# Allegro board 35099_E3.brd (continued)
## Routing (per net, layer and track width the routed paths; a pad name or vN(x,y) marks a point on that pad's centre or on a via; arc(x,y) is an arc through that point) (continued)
P1V8_CODEC: length 228.1
  TOP w0.203: C30.1 44.8,95.6 U8.6 ; C27.1 44.54,96.77 43.76,96 U8.7
  TOP w0.508: v1(101.43,7.49) U41.5 C337.1 J31.2 ; v1(8.66,2.91) 8.36,2.91 7.85,2.4 R377.1 ; U40.5 7.78,7.19 C336.1 8.47,7.55 v1(8.95,8.03) ; JS2.1 44.96,101.62 C21.1 C27.1 C30.1 ; R378.3 v1(100.66,3.99)
  L4_IN2 w0.508: v1(8.95,8.03) 8.95,43.42 2.05,50.32 2.05,65.81 25.82,89.57 v1(31.79,89.57)
  BOTTOM w0.508: v1(101.43,7.49) 100.66,6.72 v1(100.66,3.99) ; v1(8.95,8.03) 8.66,7.74 v1(8.66,2.91) 8.9,2.68 58.17,2.68 64.14,8.64 100.23,8.64 J31.2 J31.1
  vias: v1(32.41,90.46) v1(32.45,88.91) v1(33.22,89.66) v1(33.78,88.87) v1(33.87,90.53)
P5V_TRG_JTAG: length 6.5
  TOP w0.508: J19.13 78.87,76.93 78.36,76.42 TP12.1 77.65,79.17 77.6,79.22
VBAT: length 41.3
  TOP w0.254: U20.18 120.78,53.34 120.06,53.34 C80.1 R107.1 115.68,54.49 TP27.1 115.59,55.43 v1(115.99,55.83)
  L4_IN2 w0.508: v1(115.99,55.83) 124.12,55.83 125.86,57.57 141.82,57.57 J21.1
VBAT_BKUP: length 17.6
  TOP w0.203: U20.13 123.96,52.91 124.46,53.41 v1(124.5,53.41)
  TOP w0.254: R107.2 118.59,57.1 120.69,57.1 121.96,58.37 TP29.1 v1(126.44,58.37)
  L3_IN1 w0.508: v1(124.5,53.41) 124.5,56.42 v1(126.44,58.37)
  BOTTOM w0.254: C131.1 v1(124.5,53.41)
VBUS0_TARGET: length 63.7
  TOP w0.102: 97.22,61.77 97.22,61.43 97.38,61.28 98.17,61.28
  TOP w0.114: 97.22,61.77 U18.R16 ; v1(134.62,68.2) 133.78,67.36 121.11,67.36 115.02,61.28 98.17,61.28
  TOP w0.508: v1(148.67,78.28) R55.1 R54.2
  L4_IN2 w0.254: v1(148.67,78.28) 146.86,78.28 143.89,75.31 143.89,71.37 140.72,68.2 v1(134.62,68.2)
VDD1V8: length 38.2
  TOP w0.229: v2(96.47,62.52) U18.R15 ; U18.F13 v2(95.47,66.02) U18.G14 ; v2(95.47,70.02) U18.A13 ; v2(97.47,67.52) 97.47,67.52 U18.C17 U18.C16 ; v2(96.47,66.52) U18.E15 ; v2(93.97,68.02) U18.B11 ; v2(91.47,64.02) U18.L4
  L3_IN1 w0.229: v2(97.47,67.52) 97.47,67.74 96.69,68.52 94.47,68.52 v2(93.97,68.02)
  L3_IN1 w0.254: v2(97.47,67.52) 97.47,67.25 96.75,66.52 v2(96.47,66.52)
  L4_IN2 w0.229: v2(91.47,64.02) 91.47,63.62 90.55,62.7 90.55,61.85 90.86,61.54 95.79,61.54 96.47,62.22 v2(96.47,62.52) v2(96.47,66.52) 95.97,66.52 v2(95.47,66.02)
  BOTTOM w0.254: JP28.1 95.47,75.52 v2(95.47,70.02) 95.21,69.76 C118.1 94,69.29 C103.1 94,68.05 v2(93.97,68.02) ; C106.1 v2(96.47,66.52) ; C123.1 96.81,62.18 v2(96.47,62.52) ; C104.1 v2(91.47,64.02)
VDD_ACCEL: length 11.4
  TOP w0.254: U6.14 C29.1 C28.1 83.62,91.96 JP15.2
VDD_AMP: length 11.4
  L4_IN2 w0.508: v1(45.37,74.37) 45.37,71.57 47.28,69.67 47.28,68.27 47.03,68.02 46.39,68.02 45.14,66.77 v1(45.14,65.06)
  vias: v1(40.42,85.92) v1(41.06,85.92) v1(41.82,85.92)
VDD_CODEC: length 28
  TOP w0.203: U8.4 44.35,94.8 C33.1
  TOP w0.254: C329.1 51.44,97.84 U35.6 v1(54.41,97.84) U35.3 C333.1 ; v1(51.03,99.42) 51.46,99.85 R411.1 ; U36.3 v1(54.88,100.35) U36.6 ; R412.1 v1(59.03,100.56)
  TOP w0.508: JS3.1 47.4,100.8 47.4,94.99 46.16,93.75 C33.1
  BOTTOM w0.254: v1(51.03,99.42) 52.83,99.42 v1(54.41,97.84)
  vias: v1(34.12,99.33) v1(34.12,98.18) v1(34.76,98.82) v1(35.18,98.21) v1(35.31,99.35)
VDD_LDO_3V3: length 129.6
  TOP w0.381: U27.6 120.77,83.66 R50.1 121.42,83.57 v1(121.69,83.83) ; U28.6 119.9,86.53 120.26,86.88 C39.1 v1(121.92,86.88)
  TOP w0.508: R60.2 136.82,72.42 v1(136.72,72.52) ; v1(109.98,78.87) 109.98,77.76 SH4.1
  L3_IN1 w0.508: v1(121.92,86.88) 122.43,86.37 122.43,84.57 v1(121.69,83.83) 119.11,83.83 113.5,78.22 110.63,78.22 v1(109.98,78.87) 109.86,78.99 109.86,86.86 107.53,89.19 92.92,89.19 JP15.1
  L4_IN2 w0.508: v1(135.06,38.79) 135.06,26.09 JS15.2
  BOTTOM w0.508: v1(135.06,38.79) 134.37,39.48 134.37,56.77 136.72,59.12 v1(136.72,72.52) 125.4,83.83 v1(121.69,83.83)
VDD_LINK: length 16.5
  TOP w0.305: U5.6 104.53,97.33 C25.2 ; C36.2 104.57,90.75 U10.6 ; U2.6 105.77,106.06 105.75,106.07 C10.2
  TOP w0.381: 101.53,100.93 U3.8
  TOP w0.508: v1(105.97,98.17) 105.99,98.15 C25.2 ; v1(107.57,96.57) 107.06,96.06 R41.1 ; v1(102.04,99.84) 101.52,100.36 C16.2 101.53,100.93 ; R16.1 v1(103.02,109.5) ; C10.2 v1(105.16,105.05) ; v1(102.06,94.61) 101.57,94.13 R43.1 ; v1(111.89,119.81) 110.82,119.81 J2.1 ; v1(103.05,89.96) C36.2
  TOP w0.762: C12.1 JP2.2
VDD_MEM: length 28.1
  TOP w0.254: v1(63.04,53.82) 63.04,54.82 v1(63.54,55.32) R71.2 63.5,56.31 62.74,57.06 R362.1 ; v1(63.04,53.82) U19.B4 ; v1(63.04,53.82) 60.05,53.82 R69.1 ; R363.1 v1(57.54,51.32) ; U108.D1 v1(83.53,49.66) R240.1 ; U108.E4 v1(85.53,53.32) ; U108.B4 v1(82.05,52.8) ; U19.D1 v1(65.54,49.32) ; U19.E4 v1(67.04,53.82) ; R241.1 v1(78.53,54.32)
  BOTTOM w0.254: C130.1 67.03,53.81 v1(67.04,53.82) 67.05,53.81 C133.1 ; C219.1 82.05,52.01 v1(82.05,52.8) ; R71.2 v1(63.54,55.32) ; C129.1 63.03,53.82 v1(63.04,53.82) 63.08,53.85 C132.1 ; C128.1 65.55,49.32 v1(65.54,49.32) R66.1 C317.1 C128.1
  BOTTOM w0.508: C218.1 83.53,49.66 v1(83.53,49.66) ; C217.1 v1(85.53,53.32)
VDD_PMOD: length 103.4
  TOP w0.762: JS9.1 61.87,71.47 61.87,60.47 58.62,57.22 54.21,57.22 52.22,55.24 52.22,47.79 v1(45.67,41.23)
  BOTTOM w0.254: C134.2 J36.11
  BOTTOM w0.508: J36.12 J36.11
  BOTTOM w0.762: J36.11 4.06,22.11 4.85,21.33 25.76,21.33 v1(45.67,41.23)
VDD_RST: length 7.9
  TOP w0.254: U32.5 147.07,14.28 147.34,14.01 147.34,11.17 145.95,9.78 R132.2 144.65,9.78 144.46,9.59 U24.14
VDD_TARGET: length 168.2
  TOP w0.254: R1.1 v1(126.52,120.12) ; R123.1 v1(100.58,37.08) ; R98.1 JS13.2
  L4_IN2 w0.508: JS11.2 122.65,58.67 128.15,64.18 128.15,78.65 124.97,81.83 124.97,103.25 126.52,104.8 v1(126.52,120.12) ; v1(100.58,37.08) 104.01,37.08 107.31,40.39 139.08,40.39 JS13.2
  BOTTOM w0.254: JS11.2 122.03,58.67 128.27,52.43 128.27,47.88 119.96,39.57 106.63,39.57 104.14,37.08 v1(100.58,37.08)
VDDA_ADC1V8: length 13.5
  TOP w0.229: U18.E4 90.97,67.02 v2(90.47,66.52)
  BOTTOM w0.254: v2(90.47,66.52) 90.32,66.37 C109.1 81.1,66.37 JP25.2
VDDA_AO: length 24.3
  TOP w0.229: v2(95.97,67.52) U18.D13 U18.C13 v2(95.97,68.02)
  L3_IN1 w0.254: v1(109.86,67.86) 106.61,67.86 103.15,71.32 101.78,71.32 v1(100.52,72.58)
  L4_IN2 w0.254: JP26.2 v1(109.86,67.86)
  BOTTOM w0.229: C101.1 95.97,69.26 v2(95.97,68.02) 95.97,67.52 v2(95.97,67.52)
  BOTTOM w0.254: v1(100.52,72.58) 100.52,71.83 98.45,69.76 C101.1 ; C102.1 v2(95.97,68.02)
VDDA_BIAS: length 7.4
  TOP w0.229: U18.C4 90.97,68.52 v2(90.97,68.52)
  BOTTOM w0.254: C338.1 v2(90.97,68.52) 90.97,72.37 91.23,72.63 JP24.2
VDDCORE: length 9.4
  TOP w0.229: U18.J4 v2(91.47,65.02) ; v2(90.97,62.02) 90.97,62.02 U18.R5 ; U18.J14 v2(95.47,65.02) ; U18.F14 95.97,66.52 v2(95.47,67.02) ; U18.R14 v2(95.97,62.52) ; U18.P9 v2(93.47,63.02) ; U18.D9 v2(93.47,67.02) ; U18.C5 91.47,68.02 v2(90.97,67.52)
  BOTTOM w0.254: C126.1 v2(95.97,62.52) ; C119.1 v2(93.47,63.02) ; v2(93.47,67.02) 93.63,67.18 C112.1 ; C107.1 v2(90.97,67.52) ; C108.1 v2(95.47,67.02) ; v2(95.47,65.02) 95.31,64.87 C115.1 ; C125.1 v2(90.97,62.02) ; C114.1 v2(91.47,65.02)
VDDE_A: length 16.8
  TOP w0.203: v1(46.94,78.18) U12.A3 U12.B3 U12.C3 U12.C4 ; v1(47.14,67.26) U17.A3 U17.B3 U17.C3 U17.C4 U17.D4
  TOP w0.254: v1(47.14,67.26) 47.95,67.26 C71.1 ; U34.14 C328.1 48.53,82.84 v1(49.07,82.3) 49.28,82.09 49.28,79.27 48.49,78.49 C52.1 47.25,78.49 v1(46.94,78.18) ; U16.5 C63.1 52.03,67.26 v1(51.85,67.26)
  TOP w0.381: U15.5 52.47,73.28 v1(52.46,73.28)
VDDIO: length 12.8
  TOP w0.229: U18.P11 v2(94.47,63.02) U18.N12 U18.P12 U18.P11
  L3_IN1 w0.305: v2(94.47,63.02) U18.P12 95.43,62.07 97.17,62.07 JP27.1
  BOTTOM w0.229: C124.1 94.23,62.79 v2(94.47,63.02)
  BOTTOM w0.254: v2(94.47,63.02) 94.81,63.02 C105.1
VDDIO1: length 123.6
  TOP w0.203: U7.14 98.78,97.76 99.19,98.17 v1(99.3,98.17)
  TOP w0.254: R410.1 58.36,100.64 v1(58.06,100.64) 57.63,100.64 57.42,100.85 U36.7 ; v1(51.01,83.3) 51.01,83.31 U30.5 50.54,84.46 50.24,84.76 C322.1 ; R409.1 v1(51.59,102.16) ; R140.1 v1(75.72,100.82) ; v1(51.33,96.39) C330.1 51.38,97.19 U35.7 ; R139.1 v1(83.61,104.82) ; R138.1 v1(75.69,99.65) ; R137.1 v1(79.07,105.49)
  TOP w0.508: R116.1 v1(88.62,102.68) ; R383.1 R413.1 R414.1 v1(98.95,82.26) ; R130.1 v1(60.54,110.65) ; R10.1 v1(55.73,112.95) ; v1(97.09,97.62) 97.08,97.61 R39.2 ; R84.1 R83.1 127.51,46.22 C332.1 127.66,45.51 v1(127.69,45.49) ; R133.1 JP23.1 ; R58.1 v1(72.16,75.41) ; R145.1 v1(89.41,96.11) ; R117.1 v1(88.67,101.35) ; JS7.2 JS9.2
  TOP w0.762: D5.A JP2.1
  L3_IN1 w0.508: v1(51.01,83.3) 56.35,83.3 JS7.2 ; v1(127.69,45.49) 128.42,45.49 131.06,48.13 131.06,65.58 127.23,69.42 109.06,69.42 106.76,71.72 106.76,74.6 105.72,75.64 102.28,75.64 JP23.1
  BOTTOM w0.254: v1(51.59,102.16) 50.44,101.02 50.44,97.28 v1(51.33,96.39) ; v1(72.16,75.41) 70.25,77.32 70.25,86.48 70.67,86.89 R105.1
VDDIO1_MCU: length 28.6
  TOP w0.229: U18.K13 v2(95.97,64.52) U18.L14 ; U18.E6 v2(92.47,67.02) U18.E8 ; v2(94.97,65.52) U18.H13 U18.H14 ; v2(93.97,66.52) U18.E10
  L4_IN2 w0.229: v2(95.97,64.52) 95.97,65.27 95.72,65.52 v2(94.97,65.52) 94.22,65.52 93.97,65.77 v2(93.97,66.52) 92.97,66.52 v2(92.47,67.02)
  L5_PWR w0.229: v2(92.47,67.02) 92.47,68.12 93.57,69.22 98.46,69.22 102.19,72.94 102.19,75.53 JP23.2
  BOTTOM w0.254: v2(92.47,67.02) 92.63,66.87 C110.1 ; C117.1 v2(95.97,64.52) ; C113.1 v2(94.97,65.52)
ACC_INT1: length 5.4
  TOP w0.114: R40.1 R138.2 77.06,98.9 77.79,99.63 U6.11
ACC_INT2: length 6.6
  TOP w0.114: TP37.1 78.31,104.06 R137.2 79.07,101.09 79.54,100.63 U6.9
ACCEL_RST_8700: length 9.4
  TOP w0.114: R144.2 87.39,94.42 86.76,93.78 83.58,93.78 82.29,95.07 R141.1 U6.16
ALT_INT_AMP: length 14.3
  TOP w0.114: U34.5 45.19,84.93 v1(44.72,85.4)
  L3_IN1 w0.114: v1(44.72,85.4) 44.54,85.58 44.54,88.71 48.54,92.71 JP6.3
ALT_INT_CODEC: length 1
  TOP w0.114: R48.1 R401.2
BOOT0_LED: length 4.6
  TOP w0.254: R6.2 R7.1 132.23,114.83 132.42,114.65 U1.K2
BOOT1: length 3.7
  TOP w0.114: U1.K1 134.11,113.33 134.95,114.17 R9.1
BOOT2: length 5.6
  TOP w0.114: R29.2 v1(126.87,103.89)
  TOP w0.254: U1.C6 v3(128.82,107.33)
  BOTTOM w0.114: v3(128.82,107.33) 126.87,105.38 v1(126.87,103.89)
BOOT3: length 4
  TOP w0.114: U1.B10 R21.1
BRDG_INTR-ISP_DIR: length 27
  TOP w0.114: U1.J7 128.02,112.93 128.02,113.72 127.75,113.98 116.47,113.98 113.94,111.46 113.94,104.29 R25.1 113.81,103.1 U4.10
BRIDGE_INTR-ISP: length 219.2
  TOP w0.114: v1(64.14,64.25) 64.39,64.51 64.39,85 68.54,89.15 107.34,89.15 109.37,91.18 109.37,99.21 R36.1
  L3_IN1 w0.114: v1(111.38,54.74) 111.38,54.48 109.22,52.32 103.99,52.32 98.71,57.6 98.71,59.33 97.23,60.81 88.95,60.81 86.19,63.57 74.97,63.57 72.97,65.57 65.45,65.57 v1(64.14,64.25) 61.51,64.25 33.18,35.93 23.38,35.93 v1(23.37,35.94)
  L4_IN2 w0.114: JP13.2 138.3,56.39 126.87,56.39 125.22,54.74 v1(111.38,54.74)
  BOTTOM w0.114: R108.1 v1(23.37,35.94)
BRIDGE_L_INTR-ISP: length 33.1
  TOP w0.114: U1.J5 129.63,112.92 129.63,113.7 129.02,114.3 116.44,114.3 113.39,111.24 v1(113.39,107.47) ; R34.2 120.9,103.42 119.55,104.78 117.5,104.78 115.29,106.98 v1(114.55,106.98)
  BOTTOM w0.114: v1(114.55,106.98) 113.87,106.98 v1(113.39,107.47)
BRIDGE_L_MISO: length 40.7
  TOP w0.114: U26.2 v1(120.83,96.21) ; U1.J1 135.08,112.53 135.71,113.16 v1(135.76,113.16)
  BOTTOM w0.114: v1(135.76,113.16) 135.76,116.2 134.52,117.45 127.99,117.45 122.02,111.48 122.02,106.3 119.61,103.89 119.61,97.43 v1(120.83,96.21)
BRIDGE_L_MOSI: length 32.6
  TOP w0.114: U4.6 118.78,102.6 119.53,103.35 v1(120.19,103.35) ; v1(135.03,113.61) 134.34,112.93 132.82,112.93 U1.J2
  BOTTOM w0.114: v1(135.03,113.61) 135.33,113.92 135.33,115.85 134.18,117.01 128.36,117.01 122.38,111.02 122.38,105.54 v1(120.19,103.35)
BRIDGE_L_SCK: length 31.1
  TOP w0.114: U4.4 121.06,101.6 121.49,102.03 121.49,103.33 119.79,105.03 117.73,105.03 114.33,108.43 114.33,111.5 116.57,113.74 126.4,113.74 U1.K9
BRIDGE_L_SSEL: length 30.2
  TOP w0.114: U1.K10 116.55,113.33 114.76,111.53 114.76,108.51 117.98,105.28 120.14,105.28 121.84,103.58 121.84,101.83 121.12,101.1 U4.3
BRIDGE_UART_RXD: length 25
  TOP w0.114: v1(123.62,110.97) 123.67,110.93 U1.G10 ; v1(120.35,91.55) U9.4
  BOTTOM w0.114: v1(120.35,91.55) 121.52,91.55 123.62,93.65 v1(123.62,110.97)
BRIDGE_UART_TXD: length 27.7
  TOP w0.114: U9.5 120.84,92.05 v1(121.04,92.24)
  TOP w0.254: U1.G7 v3(128.02,111.33)
  BOTTOM w0.114: v1(121.04,92.24) 123.12,94.33 123.12,111.19 123.83,111.9 125.02,111.9 125.14,111.79 127.56,111.79 v3(128.02,111.33)
BT_REG_ON_3V3: length 81.1
  TOP w0.114: C319.1 Q16.3 v1(133.99,24.4) ; v1(72.33,31.93) J45.54 72.33,29.54 73.55,28.32 v1(76.2,28.32)
  L3_IN1 w0.114: v1(133.99,24.4) 80.12,24.4 v1(76.2,28.32)
  BOTTOM w0.114: v1(72.33,31.93) 71.75,31.36 R227.2
BYP_8700: length 4.1
  TOP w0.114: C31.1 86.13,99.13 U6.2
CARD_WR_PRT: length 26
  TOP w0.114: v1(109.64,29.03) 109.6,29.06 J32.11
  TOP w0.254: v1(122.34,36.65) 122.38,36.69 R308.2 R307.1
  L4_IN2 w0.114: v1(109.64,29.03) 110.61,28.06 122.13,28.06 122.84,28.77 122.84,30.17 121.7,31.32 121.7,36.01 v1(122.34,36.65)
CPCA: length 4.8
  TOP w0.203: C20.1 44.09,99.92 44.09,97.66 43.38,96.95 U8.8
CPCB: length 3
  TOP w0.203: C20.2 42.4,98.54 U8.10
CRST_8700: length 3.5
  TOP w0.114: U6.8 81.29,103.24 C143.1
CS_AP: length 4.4
  TOP w0.114: U108.A3 81.03,52.82 81.03,55.8 R248.2
CS_MX: length 3.2
  TOP w0.114: U19.C2 65.04,50.82 R350.2
DCDC_3V3: length 210.4
  TOP w0.762: C85.1 J28.8
  TOP w1.016: C85.1 10.81,50.55 11.79,49.57 11.79,46.63 16.14,42.28 16.14,5.38 J29.2
  L3_IN1 w0.508: J29.4 21.23,5.4 25.56,9.72 83.47,9.72 85.63,7.57 99.22,7.57 100.11,6.68 102.65,6.68 103.67,7.69 129.58,7.69 132.82,4.45 141.22,4.45 144.15,7.37 144.15,11.94 145.74,13.54 147.99,13.54 150.28,15.82 150.28,17.74 148.08,19.94 146.94,19.94 145.6,21.28 JS15.1
  L4_IN2 w0.508: J29.2 17.61,6.83 19.78,6.83 J29.4
DQS_AP: length 4.4
  TOP w0.114: R246.2 83.03,55.8 83.03,52.82 U108.C3
DQS_MX: length 5.4
  TOP w0.114: U19.C3 65.04,51.82 69.03,51.82 R353.2
ELECTRET_MIC: length 47.7
  TOP w0.203: R49.3 34.65,87.71 31.43,87.71 30.87,88.27 30.87,93.92 R42.1
  TOP w0.254: v1(32.11,96.34) R42.1
  BOTTOM w0.254: v1(32.11,96.34) 21.17,96.34 18.03,99.48 11.27,99.48 3.68,107.06
  BOTTOM w0.508: 3.68,107.06 4.01,107.39 D14.1
FC0_RXD: length 9
  TOP w0.114: U28.4 120.22,85.23 R50.2 122.94,84.58 J16.2
FC0_TXD: length 8.6
  TOP w0.114: U27.4 123.25,82.36 J16.1
FC1_CTS_SDA_SSEL0: length 90.4
  TOP w0.114: J47.4 41.55,59.65 R408.2 ; J31.14 86.11,11.89 86.11,38.86 v1(84.07,40.89) 84.13,40.95 R396.3
  BOTTOM w0.114: v1(84.07,40.89) 83.19,41.78 76.36,41.78 72.04,46.1 61.48,46.1 56.02,51.56 41.54,51.56 40.28,52.82 40.28,54.86 41.59,56.17 J47.4
FC1_SCK: length 6.9
  TOP w0.114: R394.3 J47.1
FC1_TXD_SCL_MISO: length 10.2
  TOP w0.114: J47.2 47.71,60.73 55.42,60.73 R395.3
FC2_SCK: length 18.6
  TOP w0.114: J47.5 40.79,61.43 50.78,61.43 52.59,63.24 R397.3
FC4_CTS_SDA_SSEL0: length 29.5
  TOP w0.114: J47.9 30.87,61.67 50.68,61.67 54.02,65.02 R398.3
FC5_CTS: length 2.7
  TOP w0.114: J45.34 v1(67.33,32.44)
  BOTTOM w0.114: v1(67.33,32.44) 67.53,32.64 R212.2
FC5_RTS: length 2.9
  TOP w0.114: J45.36 v1(67.83,31.93)
  BOTTOM w0.114: v1(67.83,31.93) 68.48,32.58 R213.2
FC5_RXD: length 2.8
  TOP w0.114: J45.22 v1(64.33,31.93)
  BOTTOM w0.114: v1(64.33,31.93) 64.67,32.27 R210.2
FC5_TXD: length 2.7
  TOP w0.114: J45.32 v1(66.83,31.93)
  BOTTOM w0.114: R211.2 66.58,32.18 v1(66.83,31.93)
HP_OUTL: length 31.8
  TOP w0.203: U8.13 41.2,98.57 40.36,99.42 40.36,100.94 40.02,101.28 34.35,101.28 C15.1 33.05,102.59 33.05,103.66 C11.1 33.78,108.64 J4.2
  TOP w0.254: J4.2 35.15,109.52 42.38,109.52 D3.1
HP_OUTR: length 40.9
  TOP w0.203: U8.15 40.4,98.79 C17.1 39.05,99 37.48,99 36.07,100.41 34.08,100.41 32.16,102.33 32.16,111.07 35.31,114.22 D3.2
  TOP w0.254: D3.2 45.21,114.24 C2.1 42.38,117.09 J4.3
I2C_SA0_8700: length 4.8
  TOP w0.114: U6.7 81.79,102.01 82.82,103.04 R139.2 82.81,104.07 R135.1
I2C_SA1_8700: length 5.5
  TOP w0.114: U6.10 79.27,100.13 77.83,101.57 R140.2 76.57,102.53 R136.1
I2PIO2_0-SD0_D(0)_SCL: length 18.6
  TOP w0.114: JS6.1 R126.2
  TOP w0.254: U1.D6 v3(128.82,108.13)
  BOTTOM w0.114: JS6.1 130.56,98.81 129.53,99.83 126.83,99.83 126.19,100.48 126.19,106.85 127.06,107.72 128.4,107.72 v3(128.82,108.13)
I2PIO2_0-SD0_D(0)_SDA: length 16.4
  TOP w0.114: JS5.1 R127.2
  TOP w0.254: U1.E6 v3(128.82,108.93)
  BOTTOM w0.114: JS5.1 126.49,99.45 125.78,100.16 125.78,107.04 127.26,108.52 128.4,108.52 v3(128.82,108.93)
I2S_ALT_INT: length 17.1
  TOP w0.114: v1(44.85,80.95) 45.19,81.3 U34.10 ; U15.4 51.59,74.1 53.1,75.62 53.1,80.19 52.38,80.92 v1(50.97,80.92)
  BOTTOM w0.114: v1(44.85,80.95) 44.85,80.96 45.31,81.42 50.47,81.42 v1(50.97,80.92)
I2S_BCLK_AMP: length 16.8
  TOP w0.114: U17.B1 45.54,68.44 v1(45.86,68.76) ; U34.12 46.12,81.73 v1(46.12,80.7) 45.54,80.12 U12.B1
  TOP w0.152: U12.B2 U12.B1 ; U17.B2 U17.B1
  BOTTOM w0.114: v1(45.86,68.76) 45.86,80.45 v1(46.12,80.7)
I2S_BCLK_CODEC: length 73.4
  TOP w0.114: v1(54.12,50.51) v1(54.12,55.11)
  TOP w0.152: R400.2 42.41,87.68 41.15,88.95 v1(41.15,89.53) 41.6,89.99 U8.29
  BOTTOM w0.114: R215.2 60.13,34.69 60.13,35.92 59.69,36.36 59.69,37.17 54.36,42.5 54.36,50.16 54.12,50.4 v1(54.12,50.51) ; v1(41.15,89.53) 41.15,88.8 42.24,87.71 48.06,87.71 51.94,83.82 51.94,82.04 52.96,81.03 52.96,73.15 54.49,71.62 54.49,55.47 v1(54.12,55.11)
I2S_DAI_AMP: length 19.9
  TOP w0.114: v2(44.74,79.95) 45.69,80.9 U34.11
  TOP w0.152: v2(44.74,79.95) U12.D1 ; v2(44.74,68.51) U17.D1
  L4_IN2 w0.152: v2(44.74,79.95) 44.19,79.95 43.78,80.36 41.98,80.36 41.58,79.96 41.58,73.81 44.74,70.65 v2(44.74,68.51)
I2S_DAI_CODEC: length 70.7
  TOP w0.114: v1(55.61,50.58) v1(55.61,55.11) ; R404.2 v1(42.37,89.52)
  TOP w0.152: v1(42.37,89.52) 42.4,89.55 U8.31
  BOTTOM w0.114: R217.2 61.81,36.36 55.14,43.03 55.14,50.11 v1(55.61,50.58) ; v1(42.37,89.52) 47.39,89.52 53.85,83.06 53.85,75.06 55.37,73.53 55.37,55.35 v1(55.61,55.11)
I2S_DAO_AMP: length 39.6
  TOP w0.152: U17.C1 v2(45.14,68.78) ; U12.C1 v2(45.14,79.56)
  L3_IN1 w0.076: v2(45.14,79.56) 45.13,79.55 44.35,79.55 44.29,79.6
  L3_IN1 w0.114: 44.29,79.6 43.96,79.94 43.96,88.63 49.11,93.78 55.06,93.78 JP7.3
  L4_IN2 w0.152: v2(45.14,68.78) 45.14,70.79 41.9,74.03 41.9,76.31 v2(45.14,79.56)
I2S_DAO_CODEC: length 87.6
  TOP w0.114: v1(56.39,55.12) 56.05,54.78 56.05,50.08 v1(55.63,49.66) ; U8.32 42.8,91.44 v1(43.08,91.16) R402.2 ; U35.4 v1(55.9,98.49)
  L4_IN2 w0.114: v1(55.9,98.49) 52.58,95.18 49.17,95.18 45.15,91.16 v1(43.08,91.16)
  BOTTOM w0.114: R218.2 62.77,35.94 55.63,43.08 v1(55.63,49.66) ; v1(43.08,91.16) 43.08,90.91 44.07,89.92 47.5,89.92 54.48,82.93 54.48,75.31 55.75,74.04 55.75,55.75 v1(56.39,55.12)
I2S_WS_AMP: length 16.5
  TOP w0.114: v1(46.63,68.75) U17.A1 ; U12.A1 45.94,79.5 v1(46.69,80.26) U34.13
  BOTTOM w0.114: v1(46.63,68.75) 47.66,69.78 47.66,79.29 v1(46.69,80.26)
I2S_WS_CODEC: length 71.3
  TOP w0.114: R399.2 42.15,88.63 v1(41.81,88.98) ; v1(54.87,50.54) v1(54.87,55.09)
  TOP w0.152: v1(41.81,88.98) 41.81,89.71 42,89.91 U8.30
  BOTTOM w0.114: v1(41.81,88.98) 47.29,88.98 53.34,82.93 53.34,73.79 54.87,72.26 v1(54.87,55.09) ; v1(54.87,50.54) 54.74,50.4 54.74,42.67 60.07,37.34 60.07,36.32 60.58,35.81 60.58,34.75 R216.2
IF_DETECT: length 42.3
  TOP w0.114: R28.1 123.93,102.11 120.5,105.53 118.19,105.53 115.21,108.51 v1(115.21,111.37)
  TOP w0.508: J2.9 105.64,119.86 v1(104.42,119.86) JS1.2
  L3_IN1 w0.114: v1(104.42,119.86) 109.3,119.86 114.68,114.48 114.68,111.9 v1(115.21,111.37)
IF_JTAG_TDI: length 25.9
  TOP w0.114: R26.2 98.3,104.62 98.3,105.05 95.2,108.15 95.2,110.9 96.34,112.04 105.65,112.04 106.98,113.37 v1(106.98,113.45) 106.98,115.77 J2.8
  BOTTOM w0.114: D13.1 106.98,114.71 v1(106.98,113.45)
IF_RST: length 243.5
  TOP w0.114: JP17.1 94.56,93.66 92.1,96.13 92.1,104.92 94.02,106.84 94.02,111.26 96.6,113.84 v1(105.54,113.84) 105.54,115.7 J2.10 ; v1(76.33,85.32) J19.10 ; SH11.1 75.69,112.01 77.37,110.34 77.37,107.9 73.28,103.81 73.28,93.11 v1(74.93,91.46) ; U24.9 v1(140.53,11.46)
  L3_IN1 w0.114: v1(75.56,25.78) 75.56,24.11 85,14.68 137.32,14.68 v1(140.53,11.46)
  L4_IN2 w0.114: v1(74.93,91.46) 74.93,88.9 75.56,88.27 75.56,86.08 v1(76.33,85.32) 77.6,84.04 77.6,59.16 74.44,56 74.44,39.98 75.56,38.86 v1(75.56,25.78)
  BOTTOM w0.114: v1(105.54,113.84) 105.54,115.31 106.29,116.07 D13.3 ; R148.2 102.36,85.72 101.47,86.61 100.84,86.61 100.2,87.25 100.2,89.66 99.06,90.81 95.76,90.81 94.6,91.96 JP17.1 88.58,85.98 76.99,85.98 v1(76.33,85.32)
IF_TCK_SWCLK: length 93
  TOP w0.114: SH13.1 v1(75.79,109.35) ; v1(72.52,85.41) J19.4 ; v1(109.45,113.82) 109.45,115.8 J2.4 ; U7.3 v1(92.99,95.91) 92.99,103.12 JP18.1 94.56,111.15 95.83,112.42 104.83,112.42 v1(105.41,113)
  L3_IN1 w0.114: v1(92.99,95.91) 91.11,97.79 84.84,97.79 75.31,107.31 75.31,108.86 v1(75.79,109.35)
  BOTTOM w0.114: v1(72.52,85.41) 72.52,86.07 R104.1 72.96,86.14 73.28,86.46 73.28,87.07 74.46,88.26 79.84,88.26 86.76,95.18 92.25,95.18 v1(92.99,95.91) ; D13.6 109.21,114.05 v1(109.45,113.82) 108.64,113 v1(105.41,113)
IF_TDO_SWO: length 112.7
  TOP w0.114: J2.6 v1(108.2,114.02) 105.84,111.66 96.75,111.66 95.68,110.59 95.68,108.79 98.95,105.52 102.14,105.52 105.16,102.5 105.16,101.55 106.63,100.08 107.54,100.08 108.13,99.49 108.13,95.72 107.79,95.38 106.27,95.38 105.99,95.66 R41.2 104.53,96.06 U5.4 103.64,96.05 103.21,95.62 v1(100.72,95.62) 100.03,96.31 U7.11 ; v1(73.79,86.74) J19.6
  TOP w0.254: v1(73.56,91.51) 72.84,92.22 72.84,104.16 76.83,108.15 76.83,110.13 76.32,110.65 SH12.1
  L4_IN2 w0.254: v1(73.79,86.74) 73.56,86.97 v1(73.56,91.51)
  BOTTOM w0.114: D13.4 108.48,116.07 108.2,115.79 v1(108.2,114.02) ; v1(73.79,86.74) 74.65,87.6 80.62,87.6 86.61,93.6 92.33,93.6 93.82,95.09 100.19,95.09 v1(100.72,95.62)
INB_2: length 1.3
  TOP w0.229: 43.54,68.58 U17.G1 U17.G2 U17.G3
INT1_AMP: length 8.2
  TOP w0.152: U12.A5 46.41,76.91 48.94,76.91 49.76,77.72 51.86,77.72 52.47,77.12 U15.1
INT2_AMP: length 15.9
  TOP w0.152: U17.A5 46.62,65.77 48.97,65.77 51.8,68.61 51.8,69.38 50.7,70.49 50.7,74.84 51.82,75.96 U15.2
INT_B: length 61.4
  TOP w0.114: v1(110.65,72) 110.23,71.58 109.45,71.58 109.44,71.57 108.13,71.57 107.18,72.52 106.93,72.77 101.67,72.77 99.04,70.15 97.05,70.15 96.47,69.57 U18.A15
  TOP w0.203: U20.10 v1(126.53,51.55) R85.2
  L4_IN2 w0.114: v1(110.65,72) 111.25,71.39 111.25,64.39 107.19,60.33 107.19,53.21 108.08,52.32 111.12,52.32 112.96,50.49 125.83,50.49 126.53,51.19 v1(126.53,51.55)
JTAG_RESET: length 35.8
  TOP w0.114: U10.3 106.75,93.13 108.73,95.11 108.73,101.09 111.18,103.53 111.18,105.54 111.89,106.25 v1(113.33,106.25) ; U1.D10 125.25,109.3 120.42,109.3 119.91,109.8 119.91,111.07 119.53,111.46 117.68,111.46 117.48,111.26 117.48,109.1 v1(116.54,108.15)
  BOTTOM w0.114: v1(116.54,108.15) 114.63,106.25 v1(113.33,106.25)
JTAG_RESET_TXEN: length 44.8
  TOP w0.114: R47.1 102.97,91.41 U10.5 105.49,91.41 105.74,91.16 105.74,90.32 106.16,89.9 v1(106.77,89.9) ; v1(124.49,111.38) 124.54,111.33 126.42,111.33 U1.G9
  BOTTOM w0.114: v1(124.49,111.38) 124.49,110.88 124,110.4 124,93.4 120.51,89.9 v1(106.77,89.9)
JTAG_TDI: length 24.9
  TOP w0.114: U1.J10 125.95,112.6 117.65,112.6 116.34,111.28 v1(116.34,109.64) ; v1(112.42,108.23) 110.26,106.07 110.26,104.19 108.3,102.23 U3.3
  BOTTOM w0.114: v1(116.34,109.64) 113.83,109.64 v1(112.42,108.23)
JTAG_VREF: length 46
  TOP w0.114: R58.2 71.25,76.44 J19.1 70.14,79.22 69.91,79.46 69.91,85.24 v1(68.13,87.02) ; J38.12 R130.2 v1(63.22,110.01) J38.14
  L3_IN1 w0.114: v1(68.13,87.02) 68.13,92.65 59.56,101.22 59.56,108.97 60.61,110.01 v1(63.22,110.01)
LDO1_OUT: length 179.4
  TOP w0.381: R3.1 124.08,119.09 v1(123.08,118.08) 122.1,117.11 R124.1
  TOP w0.508: TP17.1 127.67,61.2 v1(125.17,63.7) ; TP17.1 128.93,54.06 R82.1 R85.1 ; TP17.1 127.16,54.81 C84.1 125.42,53.41 U20.12 ; 145.61,8.26 v1(146.85,8.26) ; R67.1 v1(129.4,50.03) ; v1(141.26,34.62) 142.15,34.62 ; R70.1 v1(129.45,48.1) ; R149.1 v1(115.52,73.99)
  L3_IN1 w0.508: TP17.1 129.4,53.58 v1(129.4,50.03) 130.03,49.4 130.03,48.68 v1(129.45,48.1) 128.49,48.1 126.49,46.1 126.49,44.2 136.07,34.62 v1(141.26,34.62) 142.68,34.62 151.17,26.13 151.17,12.57 v1(146.85,8.26)
  L4_IN2 w0.762: v1(123.08,118.08) 123.08,117.6 ; v1(109.09,85.72) 109.09,77.77 109.86,77.01 JP26.1 110.57,73.15 112.35,74.93 114.58,74.93 v1(115.52,73.99) 115.43,73.9 115.43,70.99 122.73,63.7 v1(125.17,63.7)
  L4_IN2 w1.016: v1(115.52,73.99) 116.46,73.99 120.02,77.54 120.02,79.76 123.45,83.19 123.45,101.47 122.69,102.23 122.69,112.31 123.08,112.7 123.08,117.6
  BOTTOM w0.508: 106.3,85.72 v1(109.09,85.72)
LDO2_OUT: length 102.2
  TOP w0.114: JP12.3 103.08,79.41 R89.1
  TOP w0.203: v1(123.06,53.52) U20.15
  TOP w0.254: R308.1 124.45,37.71 v1(124.5,37.66) 124.51,37.65 R310.1
  TOP w0.508: R309.1 R310.1
  L3_IN1 w0.508: v1(123.06,53.52) 123.13,53.58 TP15.1 119.63,61.11 JS11.1 107.95,58.67 106.75,57.47 JP27.2
  BOTTOM w0.508: JP12.3 107.55,79.44 109.22,81.12 113.94,81.12 118.02,77.03 118.02,66.22 TP15.1 125.58,61.11 130.72,55.97 130.72,43.89 v1(124.5,37.66)
LDO_ENABLE: length 18.6
  TOP w0.114: v1(104.34,71.84) 104.33,71.83 101.41,71.83 99.24,69.66 97.18,69.66 96.97,69.45 U18.A16
  BOTTOM w0.114: JP22.2 111.01,69.22 106.97,69.22 v1(104.34,71.84)
LED_BLUE: length 3.5
  TOP w0.152: Q3.7 149.54,46.94 Q3.6 149.54,48.79 D8.C
LED_GREEN: length 3.3
  TOP w0.152: Q4.8 150.24,41.71 Q4.3 150.66,40.93 D10.C
LED_RED: length 2.3
  TOP w0.152: D9.C 150.54,43.56 149.54,42.55 Q4.6 149.54,41.86 Q4.7
LININL: length 43.1
  TOP w0.203: U8.26 40.4,92.22 39.52,91.34 39.52,87.91 35.28,83.67 33.12,83.67 29.31,87.48 29.31,110.74 28.8,111.25 C7.1
LININL_JACK: length 29.8
  TOP w0.508: R19.1 C8.1 C7.2 25.21,111.25 D4.1 23.15,109.35 15.88,109.35 v1(15.44,109.78) 15.43,109.77 J3.2
  BOTTOM w0.508: P1.1 4.01,109.27 D14.2 13.07,109.27 13.58,109.78 v1(15.44,109.78)
LININR: length 10.7
  TOP w0.203: R49.2 36.66,86.16 38.81,88.3 38.81,93.27 39.14,93.6 U8.24
LININR_JACK: length 11.2
  TOP w0.508: J3.3 21.17,117.17 D4.2 25.21,113.28 C6.2 C4.1 R4.1
LINK2_ISP_BOOT: length 8.9
  TOP w0.114: U1.C10 119.88,107.73 118.62,108.99 JP1.1
M2_32K_3V3: length 15.7
  TOP w0.114: J45.50 71.33,31.93 74.31,34.91 79.27,34.91 80.39,33.78 80.39,32.38 R423.2 R200.2
M2_SD_CDM: length 74.2
  TOP w0.114: R202.1 v1(60.23,43.04) ; v1(125.6,36.02) 126.36,36.02 R303.3
  BOTTOM w0.114: v1(125.6,36.02) 125.2,35.61 111.65,35.61 110.4,34.36 83.09,34.36 72.12,45.34 62.52,45.34 v1(60.23,43.04)
M2_SD_CLK: length 67.8
  TOP w0.114: R201.1 v1(59.27,43.04) ; v1(118.82,36.05) 118.83,36.05 R302.3
  BOTTOM w0.114: v1(118.82,36.05) 111.62,36.05 110.17,34.6 83.19,34.6 72.08,45.72 61.95,45.72 v1(59.27,43.04)
M2_SD_DAT0: length 62.4
  TOP w0.114: R203.1 v1(61.18,43.04) ; R301.3 115.4,35.3 v1(115.84,34.85)
  BOTTOM w0.114: v1(115.84,34.85) 111.65,34.85 110.92,34.12 82.89,34.12 72.05,44.96 63.1,44.96 v1(61.18,43.04)
M2_SD_DAT1: length 57.4
  TOP w0.114: R204.1 v1(62.13,43.04) ; R300.3 112.72,35.3 v1(111.83,34.41)
  BOTTOM w0.114: v1(62.13,43.04) 63.67,44.58 71.98,44.58 82.68,33.88 111.3,33.88 v1(111.83,34.41)
M2_SD_DAT2: length 76.4
  TOP w0.114: R305.3 130.93,36.45 v1(127.46,36.45) ; R205.1 v1(63.08,43.04)
  BOTTOM w0.114: v1(63.08,43.04) 64.24,44.2 71.91,44.2 82.47,33.64 116.44,33.64 118.09,35.29 126.3,35.29 v1(127.46,36.45)
M2_SD_DAT3: length 78.1
  TOP w0.114: R206.1 v1(64.04,43.04) ; v1(130.7,34.85) 130.26,35.3 R304.3
  BOTTOM w0.114: v1(64.04,43.04) 64.81,43.81 71.85,43.81 83.08,32.58 115.89,32.58 118.29,34.98 124.15,34.98 125.93,33.2 131.11,33.2 131.42,33.5 131.42,34.13 v1(130.7,34.85)
M2_SD_RST_B: length 63.4
  TOP w0.114: v1(122.32,33.07) 121.56,32.31 R306.3 ; R208.1 v1(65.94,43.04)
  BOTTOM w0.114: v1(65.94,43.04) 71.72,43.04 82.66,32.1 121.34,32.1 v1(122.32,33.07)
M2_SD_WK_B: length 66.7
  TOP w0.114: v1(124.1,33.07) 123.33,32.31 R307.3 ; R207.1 v1(64.99,43.04)
  BOTTOM w0.114: v1(124.1,33.07) 123.59,33.58 121.97,33.58 120.73,32.34 82.87,32.34 71.73,43.48 65.43,43.48 v1(64.99,43.04)
M2_USB_DN: length 160.1
  TOP w0.114: R222.1 v1(146.2,83.87) ; v1(59.41,35.41) 59.16,35.65 59.16,36.05 59.95,36.83 59.95,37.2 60.08,37.33 J45.5
  BOTTOM w0.114: v1(59.41,35.41) 59.17,35.17 59.17,34.81 58.85,34.49 57.3,34.49 56.57,33.76 56.57,28.87 60.92,24.51 125.48,24.51 136.53,35.56 136.53,42.8 135.64,43.69 135.64,56.13 138.68,59.18 138.68,74.42 146.43,82.17 147.36,82.17 148.97,83.78 148.97,84.79 147.77,85.99 147.73,85.99 146.32,85.99 146.2,85.87 v1(146.2,83.87)
M2_USB_DP: length 161.2
  TOP w0.114: R221.1 v1(146.2,88.34) ; J45.3 59.58,37.33 59.71,37.2 59.71,36.93 58.92,36.15 58.92,35.65 58.68,35.41 v1(58.68,35.39)
  BOTTOM w0.114: v1(58.68,35.39) 58.93,35.14 58.93,34.91 58.75,34.73 57.2,34.73 56.32,33.86 56.32,28.77 60.82,24.27 125.58,24.27 136.77,35.46 136.77,42.9 135.88,43.79 135.88,56.03 138.93,59.08 138.93,74.32 146.53,81.93 147.46,81.93 149.21,83.68 149.21,84.89 147.87,86.23 147.67,86.23 146.32,86.23 146.2,86.34 v1(146.2,88.34)
MCLK_CODEC: length 18.5
  TOP w0.114: U35.5 49.83,98.49 R403.2 v1(48.59,97.25) ; U8.28 41.2,91.91 v1(40.91,91.62)
  L3_IN1 w0.114: v1(48.59,97.25) 48.59,93.84 46.37,91.62 v1(40.91,91.62)
MEM_1V8: length 10.4
  TOP w0.114: v1(76.54,50.32) 76.66,50.44 R249.1 ; R250.1 v1(79.53,57.81)
  L4_IN2 w0.114: v1(79.53,57.81) 79.53,53.32 v1(76.54,50.32)
MICBIAS: length 7.2
  TOP w0.203: U8.20 38,95.2
  TOP w0.254: C32.1 36.83,94.97 36.17,94.31 33.96,94.31 R42.2
  TOP w0.381: C32.1 36.88,95.2 38,95.2
MICVDD: length 3.9
  TOP w0.203: C26.1 38.57,95.6 U8.19
  TOP w0.381: C26.1 37.37,96.79 L2.2
MODESEL0: length 64.1
  TOP w0.114: v1(108.88,72.01) 108.88,72 107.87,73.01 101.57,73.01 98.94,70.39 96.95,70.39 96.22,69.65 96.22,68.28 U18.C15
  TOP w0.203: R81.1 R70.2 v1(126.98,48.78) 126.98,49.11 125.94,50.15 U20.7
  L4_IN2 w0.114: v1(126.98,48.78) 125.78,49.98 112.45,49.98 111.12,51.31 107.57,51.31 106.3,52.58 106.3,60.83 108.88,63.42 v1(108.88,72.01)
MODESEL1: length 58.8
  TOP w0.114: U18.B16 97.22,68.77 97.22,69.31 97.34,69.42 99.34,69.42 101.31,71.39 105.8,71.39 108.72,68.47 v1(110.52,68.47) ; v1(126.77,50.01) 126.79,50.03 R67.2
  TOP w0.203: U20.8 126.23,50.55 v1(126.77,50.01) ; R68.1 R67.2
  L4_IN2 w0.114: v1(126.77,50.01) 126.55,50.24 112.7,50.24 111.12,51.82 107.82,51.82 106.81,52.83 106.81,60.83 110.52,64.55 v1(110.52,68.47)
NRESET_OSPI: length 156.8
  TOP w0.114: v1(149.13,12.77) 151.04,14.68 151.04,15.69 150.4,16.33 v1(148.88,16.33) 148.14,17.07 R373.1 ; R351.1 v1(57.54,53.32) ; R128.2 139.64,5.51 TP34.1
  TOP w0.152: TP34.1 141.18,7.06 U24.10 141.18,10.59 v1(142.49,11.9) 142.49,9.6 U24.12
  TOP w0.254: R69.2 R351.1
  L3_IN1 w0.114: v1(148.88,16.33) 147.68,17.53 137.27,17.53 137.07,17.73 137.07,24.2 135.61,25.66 80.89,25.66 v1(78.74,27.81) ; v1(57.54,53.32) 60.16,55.93 v1(75.18,55.93)
  L4_IN2 w0.114: v1(75.18,55.93) 75.18,39.98 80.01,35.15 80.01,29.08 v1(78.74,27.81)
  BOTTOM w0.114: v1(149.13,12.77) 147.1,10.74 144.94,10.74 143.78,11.9 v1(142.49,11.9)
NRESET_OSPI_AP: length 107.2
  TOP w0.114: U32.6 145.57,13.63 R372.2 145.56,17.07 TP40.1 ; TP40.1 R373.2 ; TP40.1 v1(145.58,18.23) ; R242.2 v1(76.54,52.32)
  L3_IN1 w0.114: v1(145.58,18.23) 143.87,19.94 139.19,19.94 137.7,21.43 137.7,24.58 135.8,26.49 80.83,26.49 v1(79.5,27.81)
  L4_IN2 w0.114: v1(76.54,52.32) 75.77,51.55 75.77,40.31 80.54,35.54 80.54,28.85 v1(79.5,27.81)
NRESET_PB: length 218.2
  TOP w0.114: U24.1 143.78,16.85 143.29,17.34 139.1,17.34 138.97,17.22 138.97,7.57 v1(139.61,6.93)
  TOP w0.152: v1(84.24,10.74) 84.84,11.34 84.84,35.18 v1(82.8,37.21) ; R3.2 C1.1 R2.1 121.02,120.71 v1(120.9,120.83)
  L3_IN1 w0.114: v1(139.61,6.93) 138.28,8.26 86.72,8.26 v1(84.24,10.74)
  L3_IN1 w0.152: v1(120.9,120.83) 120.9,115.86 113.88,108.84 100.33,108.84 98.29,106.8 94.76,106.8 93.12,105.16 v1(90.3,105.16)
  L4_IN2 w0.152: v1(90.3,105.16) 90.3,97.89 86.61,94.2 86.61,85.5 87.86,84.25 87.86,77.51 87.51,77.16 87.51,62.27 88.57,61.2 88.57,59.31 89.23,58.65 89.23,57.9 87.14,55.81 87.14,45.62 82.8,41.28 v1(82.8,37.21)
NRESET_POR: length 193.5
  TOP w0.114: v1(140.81,16.9) 141.18,16.53 U24.5
  L4_IN2 w0.152: v1(10.15,41.99) 11.44,40.69 11.44,5.68 14.26,2.87 61.25,2.87 66.46,8.07 107.1,8.07 108.37,9.34 134.91,9.34 v1(136.94,11.38)
  BOTTOM w0.114: v1(136.94,11.38) 140.81,15.25 v1(140.81,16.9) 140.37,17.34 139.35,17.34 138.08,18.61 138.08,29.79 JS17.2
  BOTTOM w0.152: R106.2 v1(10.15,41.99)
NRESET_TRGT: length 301.6
  TOP w0.114: v1(98.93,41.02) 99.31,41.02 101.22,39.12 v1(101.22,37.85) 100.23,37.85 99.95,37.56 99.95,34.92 110.53,24.35 110.53,19.9 111.81,18.61 JP14.2 ; v1(100.76,108.31) 103.35,110.9 109.29,110.9 TP39.1 116.63,115.65 121.82,115.65 R124.2 ; v1(149.12,13.58) 149.07,13.63 U32.1 ; v1(53.99,73.92) 53.34,74.57 53.34,80.46 52.59,81.21 51.96,81.21 51.66,81.5 U30.2 ; U24.6 140.53,13.72 v1(141.83,12.42) ; v1(108.32,71.05) 108.3,71.05 107.08,72.28 104.16,72.28 104.15,72.27 v1(102.36,72.27) 101.51,72.27 99.14,69.9 97.12,69.9 96.72,69.51 96.72,68.77 U18.B15
  TOP w0.152: U24.11 v1(141.83,7.31) 141.83,5.63 TP32.1 ; v1(141.83,12.42) U24.4 ; v1(141.83,12.42) 143.13,13.72 U24.2 ; v1(141.83,12.42) 141.81,12.39 140.62,12.39 139.88,11.65 U24.8 ; R124.2 Q8.1 ; v1(53.99,73.92) 51.82,71.74 U16.2 ; R125.1 v1(100.24,94.44) 100.24,94.45 101.02,95.22 105.42,95.22 v1(106.52,94.13)
  L3_IN1 w0.152: v1(53.99,73.92) 56.2,76.13 59.83,76.13 65.93,82.22 71.82,82.22 v1(76.2,86.6)
  L4_IN2 w0.152: v1(108.32,71.05) 108.32,90.41 108.32,90.41 108.32,90.99 108.31,91 108.31,92.34 v1(106.52,94.13)
  BOTTOM w0.114: JP14.2 141.83,16.64 v1(141.83,12.42) ; v1(141.83,12.42) v1(141.83,7.31) ; v1(141.83,12.42) 144.28,12.42 145.2,11.5 147.04,11.5 v1(149.12,13.58) ; v1(98.93,41.02) 97.79,42.16 97.79,46.99 98.3,47.5 98.3,68.2 98.29,68.2 v1(102.36,72.27) ; v1(100.24,94.44) 101.19,95.39 101.19,100.04 100.02,101.22 100.02,107.56 v1(100.76,108.31)
  BOTTOM w0.152: JP16.3 108.26,44.89 v1(101.22,37.85) ; v1(100.24,94.44) 99.02,93.22 93.85,93.22 87.24,86.6 v1(76.2,86.6)
NTRST_LINK2: length 22.9
  TOP w0.114: U1.B4 131.22,106.53 131.22,103.86 R33.2 133.55,103.12 v1(133.6,103.17) ; TP3.1 140.89,114.25 v1(140.89,113.54)
  BOTTOM w0.114: v1(140.89,113.54) 140.89,110.46 v1(133.6,103.17)
ON_B: length 17.3
  TOP w0.203: U20.4 123.56,49.13 124.28,48.41 v1(124.7,48.41)
  L4_IN2 w0.114: JP16.2 111.88,46.17 122.46,46.17 v1(124.7,48.41)
ON_B_SW: length 59.1
  TOP w0.114: R89.2 v1(104.59,78.39)
  TOP w0.254: SW4.3 SW4.4 107.81,47.15 JP16.1
  BOTTOM w0.114: v1(104.59,78.39) 103.3,78.39 102.26,77.36 102.26,73.62 102.92,72.97 106.34,72.97 108.17,74.8 112.79,74.8 113.95,73.64 113.95,62.39 110.63,59.07 JP16.1
OUTN_1: length 38.3
  TOP w0.762: R57.2 R59.2 ; R57.2 L6.2 ; R57.2 29.72,76.07 13.38,92.41 J11.2
OUTN_2: length 36.2
  TOP w0.762: R64.2 C73.1 29.9,64.9 18.77,76.03 J20.2 ; R64.2 R65.2 ; R64.2 L10.2
OUTP_1: length 38.7
  TOP w0.762: R52.2 C45.1 14.05,97.41 J11.1 ; R52.2 L5.2 ; R52.2 R51.2
OUTP_2: length 36.6
  TOP w0.762: R63.2 L9.2 ; R63.2 R62.2 ; R63.2 C65.1 19.25,81.03 J20.1
P0_0: length 55.3
  TOP w0.114: v1(68.99,82.93) 68.99,71.09 74.89,65.19 83,65.19 83.83,66.02 U18.G1
  L3_IN1 w0.114: JP6.2 53.84,88.91 57.15,88.91 57.93,88.13 57.93,86.74 61.74,82.93 v1(68.99,82.93)
P0_0_CODEC_ALT_IN: length 8.7
  TOP w0.114: JP6.1 51.01,87.63 48.8,89.84 45.47,89.84 R401.1
P0_1_FC0_TX: length 90.7
  TOP w0.114: v1(73.68,71.49) 73.68,67.29 75.45,65.52 82.91,65.52 83.67,66.28 89.71,66.28 U18.G2 ; U9.12 114.56,92.05 R147.2 110.54,89.26 v1(110.54,84.33) 110.54,83.01 111.26,82.29 112.31,82.29 112.44,82.41 117.04,82.41 U27.3
  L4_IN2 w0.114: v1(73.92,81.27) 74.15,81.04 74.15,71.96 v1(73.68,71.49)
  BOTTOM w0.114: v1(110.54,84.33) 107.87,81.65 79.14,81.65 78.76,81.27 v1(73.92,81.27)
P0_2_FC0_RX: length 41.4
  TOP w0.114: R146.2 113.82,85.85 JP21.2
  TOP w0.229: v2(90.97,65.52) U18.G4
  L4_IN2 w0.114: v2(90.97,65.52) 90.96,65.52 90.01,66.47 90.01,68.07 92.49,70.55 92.49,82.05 v1(92.89,82.45)
  BOTTOM w0.114: JP21.2 110.62,85.85 107.47,82.7 93.14,82.7 v1(92.89,82.45)
P0_2_FC0_RX_EXT: length 6.1
  TOP w0.114: JP21.3 114.15,83.31 116.07,85.23 U28.3
P0_2_FC0_RX_LINK: length 3.5
  TOP w0.114: JP21.1 113.94,90.53 R46.2
P0_3: length 174.9
  TOP w0.114: J45.58 v1(73.33,31.93) ; U18.H2 84.1,65.52 82.85,64.27 75.15,64.27 v1(73.92,65.5) 68.45,70.97 68.45,83.79 v1(69.4,84.73) ; v1(78.98,108.52) 85.09,114.63 85.09,118.62 J1.3
  L3_IN1 w0.114: v1(73.33,31.93) 73.33,32.55 72.73,33.15 71.5,33.15 68.48,36.17 48.74,36.17 43.18,30.61 v1(26.92,30.61)
  L4_IN2 w0.114: v1(73.92,65.5) 73.41,65 73.41,56.81 73.4,56.79 73.4,37.6 74.42,36.58 74.42,32.33 74.02,31.93 v1(73.33,31.93) ; v1(69.4,84.73) 70.41,85.75 70.41,99.95 v1(78.98,108.52)
  BOTTOM w0.114: v1(73.33,31.93) 73.33,33.37 R415.2 ; R110.1 24.89,32.64 v1(26.92,30.61)
P0_4: length 116.2
  TOP w0.114: J45.60 v1(73.83,32.44) ; v1(78.75,109.39) 78.75,113.8 80,115.05 80,118.61 J1.5 ; v1(68.58,85.26) 68,84.67 68,68.99 v1(72.68,64.3) 73.2,63.79 83.16,63.79 84.4,65.02 U18.J1
  L4_IN2 w0.114: v1(78.75,109.39) 69.82,100.46 69.82,86.5 v1(68.58,85.26) ; v1(72.68,64.3) 72.68,62.49 72.16,61.97 72.16,37.06 73.83,35.39 v1(73.83,32.44)
  BOTTOM w0.114: R416.2 74.2,32.81 v1(73.83,32.44)
P0_5_ADC0_0: length 95.3
  TOP w0.114: v1(36.58,12.83) R99.2
  TOP w0.229: v2(91.47,66.02) U18.F4
  L3_IN1 w0.114: v1(51.07,54.57) 51.48,54.57 63.45,66.54 74,66.54 75.03,65.52 82.84,65.52 83.35,66.02 v2(91.47,66.02)
  L4_IN2 w0.114: v1(51.07,54.57) 51.07,51.45 36.58,36.96 v1(36.58,12.83)
P0_6_ADC0_8: length 92.2
  TOP w0.114: U18.E1 83.18,67.02 83.17,67.02 v1(76.76,67.02) ; v1(38.86,12.84) R100.2
  L3_IN1 w0.114: v1(51.06,55.29) 51.85,55.29 63.59,67.02 v1(76.76,67.02)
  L4_IN2 w0.114: v1(38.86,12.84) 38.86,38.1 51.69,50.93 51.69,54.65 v1(51.06,55.29)
P0_7_I2S_CLK: length 46
  TOP w0.114: R394.1 60.98,61.47 60.98,70.73 56.79,74.92 55.16,74.92 54.3,75.78 54.3,85.04 53.62,85.72 51.57,85.72 50.94,86.35 v1(47.62,86.35) ; R400.1 44.73,87.68 v1(45.34,88.29) 45.59,88.29 TP10.1 U34.3
  L3_IN1 w0.114: v1(45.34,88.29) 47.28,86.35 v1(47.62,86.35)
P0_8_I2S_WS: length 45.3
  TOP w0.114: v1(48.23,85.85) 50.67,85.85 51.06,85.46 53.51,85.46 54.05,84.92 54.05,75.66 55.05,74.67 56.69,74.67 60.6,70.75 60.6,62.86 R395.1 ; R399.1 44.28,88.82 46.61,88.82 v1(47.19,88.24) 47.67,88.24 TP9.1 46.69,86.15 U34.2
  L3_IN1 w0.114: v1(47.19,88.24) 48.23,87.21 v1(48.23,85.85)
P0_9_CODEC_DAI: length 17.7
  TOP w0.114: R404.1 44.48,89.13 48.67,89.13 51.76,86.03 58.09,86.03 JP8.1
P0_9_I2S_DAI: length 21.1
  TOP w0.114: v1(45.48,85.4) 45.69,85.19 U34.4
  L3_IN1 w0.114: v1(45.48,85.4) 44.81,86.08 44.81,88.6 47.42,91.21 58.19,91.21 JP8.3
P0_9_I2S_DATA: length 82.2
  TOP w0.114: v1(58.82,66.79) 60.09,65.52 60.09,63.11 59.2,62.22 51.91,62.22 50.77,61.08 45.52,61.08 J47.3 ; v1(66.55,66.05) 69.3,63.3 84.92,63.3 85.9,64.28 90.21,64.28 U18.L3
  BOTTOM w0.114: v1(58.82,66.79) 59.56,66.05 v1(66.55,66.05) 66.55,78.17 66.08,78.64 66.08,83.78 JP8.2
P0_10: length 98.5
  TOP w0.114: v1(80.73,91.37) 80.03,90.67 71.14,90.67 57.52,104.29 54.16,104.29 51.66,106.79 R11.2 ; v1(84.13,45.68) R396.1
  TOP w0.152: R11.2 C5.1 51.66,116.59 SW2.2 SW2.1
  L4_IN2 w0.114: v1(84.13,45.68) 84.13,45.8 80.05,49.88 80.05,74.81 80.73,75.49 v1(80.73,91.37)
P0_11: length 148
  TOP w0.114: v1(67.7,85.26) 65.91,83.48 65.91,65.92 v1(68.6,63.23) 68.77,63.06 85.02,63.06 85.99,64.02 U18.L1
  TOP w0.508: R407.2 J1.10
  L4_IN2 w0.114: v1(67.7,85.26) 69.08,86.64 69.08,100.35 79.13,110.41 79.13,114.41 J1.10 ; v1(68.6,63.23) 68.6,44.82 66.14,42.36 66.14,29.37 82.14,13.36 J31.13
P0_12: length 202.5
  TOP w0.114: U18.E3 89.97,66.52 83.52,66.52 82.95,65.96 v1(76.26,65.96) ; Q15.1 146.81,27.74 146.53,27.46 R229.2 147.38,26.84 v1(147.4,26.82)
  L4_IN2 w0.114: v1(147.4,26.82) 148.24,25.97 148.24,20.9 146.97,19.63 80.19,19.63 74.3,25.53 74.3,28.83 75.03,29.57 75.03,37.49 73.76,38.76 73.76,56.56 75.02,57.81 75.02,61.02 76.26,62.26 v1(76.26,65.96) 76.26,66.4 74.88,67.79 74.88,83.82 72.03,86.67 72.03,99.85 80.82,108.65 80.82,116.27 79.96,117.14 79.96,118.67 J1.7
P0_13: length 190.6
  TOP w0.114: Q16.1 146.67,22.14 R228.2 147.42,20.84 v1(147.48,20.9) ; U18.G3 90.22,65.77 83.97,65.77 82.88,64.68 77.09,64.68 v1(77.06,64.72)
  L4_IN2 w0.114: v1(147.48,20.9) 146.72,20.14 80.08,20.14 74.57,25.64 74.57,28.71 75.31,29.45 75.31,38.23 74.01,39.53 74.01,56.05 77.06,59.1 v1(77.06,64.72) 77.06,65.95 75.18,67.83 75.18,84.02 73.12,86.08 73.12,100.36 81.28,108.52 J1.6
P0_14: length 166.2
  TOP w0.114: R397.1 59.2,63.37 v1(58.44,64.13)
  TOP w0.152: Q4.5 149.89,42.5 150.14,42.75 v1(150.77,42.75)
  L4_IN2 w0.114: v1(58.44,64.13) 63.01,59.55 63.01,56.97 62.14,56.09 62.14,51.13 63.01,50.25 63.01,44.81 63.2,44.62 63.2,43.78 62.65,43.22 62.65,39.85 60.14,37.34 60.14,34.86 60.35,34.65 60.35,32.13 61.88,30.6 61.88,29.81 79.76,11.94 139.28,11.94 140.5,13.15 147.99,13.15 150.77,15.94 v1(150.77,42.75)
P0_15_FC2_SCL: length 169.8
  TOP w0.114: v1(90.03,81.03) 125.48,81.03 128.85,84.4 128.85,93.29 JS6.2 ; v1(84.33,79.88) 85.58,78.63 85.58,75.1 87.55,73.13 87.55,72.29 88.67,71.17 89.51,71.17 91.47,69.21 U18.A5
  L3_IN1 w0.114: v1(90.03,81.03) 88.88,79.88 v1(84.33,79.88) v1(66.93,79.88)
  L4_IN2 w0.114: v1(66.93,79.88) 53.42,66.38 53.42,63.58 50.87,61.03 36.74,61.03 36.51,60.81 J47.6 35.23,58.41 34.62,58.41 22.51,46.3 22.51,28.54 v1(23.37,27.69)
  BOTTOM w0.114: R113.1 v1(23.37,27.69)
P0_16_FC2_SDA: length 176
  TOP w0.114: v1(89.3,81.02) 89.81,81.53 125.09,81.53 128.27,84.71 128.27,93.22 JS5.2 ; U18.D6 91.97,67.89 91.72,68.14 91.72,69.3 89.61,71.41 88.77,71.41 87.79,72.39 87.79,73.23 85.82,75.2 85.82,79.29 84.48,80.64 v1(84.35,80.64)
  L3_IN1 w0.114: v1(66.95,80.64) v1(84.35,80.64) 84.73,81.02 v1(89.3,81.02)
  L4_IN2 w0.114: v1(66.95,80.64) 52.9,66.59 52.9,63.8 50.78,61.67 35.95,61.67 J47.7 33.97,58.65 21.75,46.43 21.75,26 v1(23.37,24.38)
  BOTTOM w0.114: R115.1 v1(23.37,24.38)
P0_17_FC2_SDA: length 229.3
  TOP w0.114: SH2.2 v1(87.85,104.83) ; R73.1 8.4,50.57 8.4,54.63 9.27,55.5 22.86,55.5 23.64,54.71 23.64,51.79 24,51.44 28.1,51.44 29.61,52.95 29.61,55.49 31.43,57.31 J47.8 ; v1(86.75,82.21) 86.42,81.89 86.42,75.29 88.27,73.45 88.27,72.59 88.97,71.89 89.82,71.89 92.22,69.49 92.22,67.77 U18.D7
  L3_IN1 w0.114: v1(86.75,82.21) 86.29,81.75 v1(67.03,81.75)
  L4_IN2 w0.114: v1(67.03,81.75) 67.39,81.39 67.39,78.41 66.25,77.27 66.25,75.49 57.76,67 57.76,59.7 v1(60.95,56.51) 60.95,46.95 46.69,32.68 J30.5 ; v1(86.75,82.21) 85.98,82.97 85.98,83.84 85.42,84.4 85.42,96 89.12,99.69 89.12,103.56 v1(87.85,104.83)
  BOTTOM w0.114: J47.8 34.6,62.86 50.7,62.86 51.97,61.59 51.97,55.74 53.24,54.47 58.92,54.47 v1(60.95,56.51)
P0_18_FC2_SCL: length 223
  TOP w0.114: v1(5.47,49.29) 5.23,49.29 5.22,49.28 R72.1 ; U18.B7 92.73,68.78 92.73,69.67 86.91,75.49 v1(86.91,78.23) ; SH3.2 88.49,100.2 v1(88.6,100.3)
  L3_IN1 w0.114: v1(5.47,49.29) 44.72,49.29 v1(47.62,52.2) ; v1(67.12,76.89) 68.47,78.23 v1(86.91,78.23)
  L4_IN2 w0.114: v1(86.91,78.23) 86.91,80.5 84.55,82.86 84.55,96.26 v1(88.6,100.3) ; J30.6 49.23,34.22 61.64,46.64 61.64,58.9 58,62.53 58,66.86 67.12,75.98 v1(67.12,76.89)
  BOTTOM w0.114: v1(47.62,52.2) 52.67,52.2 54.44,53.97 59.46,53.97 61.5,56.01 61.5,59.95 67.12,65.57 v1(67.12,76.89)
P0_19_ADC0_2: length 100.2
  TOP w0.114: R101.2 41.66,12.71 v1(41.54,12.83) ; v1(71.63,74.14) 71.7,74.14 71.9,74.34 83.79,74.34 89.1,69.02 U18.A1
  L3_IN1 w0.114: v1(62.76,74.14) 62.95,74.34 71.44,74.34 v1(71.63,74.14)
  L4_IN2 w0.114: v1(41.54,12.83) 41.54,39.64 52.2,50.29 52.2,61.82 54.01,63.63 54.01,65.39 v1(62.76,74.14)
P0_20_ADC0_10: length 98.7
  TOP w0.114: v1(72.26,73.74) 84.05,73.74 89.01,68.77 89.72,68.77 U18.B2 ; v1(44.2,12.81) R102.2
  L3_IN1 w0.114: v1(72.26,73.74) 71.97,73.45 63.81,73.45 v1(63.52,73.74)
  L4_IN2 w0.114: v1(44.2,12.81) 44.2,41.4 52.73,49.93 52.73,61.46 54.76,63.49 54.76,64.45 63.52,73.21 v1(63.52,73.74)
P0_21: length 73.7
  TOP w0.114: SH17.2 v1(60.07,112.55) ; U18.C7 92.97,68.52 92.97,69.77 87.36,75.38 87.36,83.12 86.88,83.6 85.72,83.6 v1(85.34,83.22) 83.28,81.17 78.6,81.17 77.6,82.17 77.6,83.29
  L3_IN1 w0.114: v1(60.07,112.55) 61.61,112.55 66.35,107.82 66.35,98.9 72.74,92.52 76.04,92.52 v1(85.34,83.22)
P0_22: length 58.9
  TOP w0.114: 78.87,85.13 78.87,85.31 79.42,85.87 86.04,85.87 88.32,83.59 88.32,77.4 89.83,75.89 89.83,74.61 93.03,71.41 v1(93.48,71.41) ; 78.87,85.13 v1(78.9,85.16) ; 78.87,85.13 J19.14 ; U18.D8 v2(92.97,68.02) ; v1(60.07,102.39) SH21.2
  L3_IN1 w0.114: v1(78.9,85.16) 74.55,89.52 71.98,89.52 64.48,97.02 64.48,97.99 v1(60.07,102.39)
  BOTTOM w0.114: v2(92.97,68.02) 92.97,70.91 v1(93.48,71.41)
P0_23_CODEC_DAO: length 26
  TOP w0.114: R402.1 44.97,89.46 48.84,89.46 51.76,86.54 55.05,86.54 JP7.1 ; U35.1 v1(55.3,96.54)
  L4_IN2 w0.114: v1(55.3,96.54) 54.63,95.88 54.63,89.13 JP7.1
P0_23_I2S_DATA_TX: length 76.5
  TOP w0.114: SH20.2 v1(60.07,104.78) ; v1(80.17,85.16) 80.14,85.13 J19.16 80.14,82.3 81.03,81.41 82.89,81.41 85.32,83.84 87.05,83.84 87.6,83.29 87.6,75.48 93.21,69.87 93.21,68.28 U18.C9
  L3_IN1 w0.114: v1(80.17,85.16) 75.32,90.02 72.48,90.02 64.98,97.52 64.98,99.87 v1(60.07,104.78)
  L4_IN2 w0.114: v1(60.07,104.78) 58.55,103.25 58.55,92.58 JP7.2
P0_24: length 59.7
  TOP w0.114: J19.18 81.44,83.32 v1(81.44,85.16) 81.91,85.63 85.94,85.63 88.08,83.49 88.08,75.68 93.73,70.03 93.73,68.78 U18.B9 ; SH19.2 v1(60.07,106.2)
  L3_IN1 w0.114: v1(60.07,106.2) 65.48,100.8 65.48,98.02 72.98,90.52 76.09,90.52 v1(81.44,85.16)
P0_25: length 59.1
  TOP w0.114: SH18.2 v1(60.07,107.57) ; v1(82.68,85.13) J19.20 84.2,83.29 85,84.08 87.15,84.08 87.84,83.39 87.84,75.58 93.47,69.95 U18.A9
  L3_IN1 w0.114: v1(60.07,107.57) 65.98,101.66 65.98,98.36 73.32,91.02 76.79,91.02 v1(82.68,85.13)
P0_26: length 99.3
  TOP w0.114: v1(82.25,75.86) 82.6,75.86 88.26,70.2 88.79,70.2 U18.A2
  TOP w0.152: v1(124.73,66.89) 137.96,66.89 151.53,53.32 151.53,46.73 150.64,45.84 150.15,45.84 149.89,46.1 Q3.2
  L3_IN1 w0.152: v1(82.25,75.86) 82.63,76.24 89.79,76.24 90.05,75.99 91.91,75.99 92.46,75.44 92.46,74.17 92.96,73.66 94.49,73.66 97.92,70.23 103,70.23 106.34,66.89 v1(124.73,66.89)
P0_27: length 69.6
  TOP w0.114: v1(56.73,73.38) 55.49,72.14 53.94,72.14 53.34,71.54 53.34,65.7 50.75,63.11 45.56,63.11 v1(44.76,62.31) ; v1(84.13,75.68) 84.13,75.02 88.46,70.69 89.25,70.69 90.73,69.21 90.73,68.78 U18.B3
  L3_IN1 w0.114: v1(84.13,75.68) 83.8,75.35 74.37,75.35 73.43,76.29 71.21,76.29 70.6,75.68 59.03,75.68 v1(56.73,73.38)
  BOTTOM w0.114: J27.4 42.95,54.99 42.95,60.5 v1(44.76,62.31)
P0_28: length 71.8
  TOP w0.114: v1(46.76,62.35) 47.27,62.86 50.84,62.86 53.85,65.87 v1(53.85,70.78) ; U18.D11 94.99,68.04 94.99,72.02 v1(94.36,72.64)
  L3_IN1 w0.114: v1(53.85,70.78) 56.52,70.78 60.36,74.63 89.08,74.63 91.02,72.68 94.32,72.68 v1(94.36,72.64)
  BOTTOM w0.114: J27.3 45.36,54.86 45.36,60.95 v1(46.76,62.35)
P0_29_FC4_TXD: length 63.3
  TOP w0.114: v1(56.53,71.42) 54.86,69.76 54.86,66.2 50.58,61.91 49.61,61.91 v1(49.17,62.35) ; R79.1 v1(46.66,57.65) ; U18.B10 93.97,70.13 89.11,74.99 v1(89.11,75.4)
  L3_IN1 w0.114: v1(89.11,75.4) 88.58,74.87 59.97,74.87 v1(56.53,71.42)
  BOTTOM w0.114: v1(46.66,57.65) 47.77,58.76 47.77,60.95 v1(49.17,62.35)
P0_30_FC4_RXD: length 65
  TOP w0.114: U18.C11 94.75,68.3 94.75,71.37 v1(92.96,73.15) ; v1(57.02,72.57) 54.36,69.9 54.36,66.03 50.67,62.35 v1(50.31,62.35) ; R80.1 v1(49.2,57.65)
  L3_IN1 w0.114: v1(92.96,73.15) 91.19,73.15 90.04,74.3 90.04,75.36 89.56,75.84 85.32,75.84 84.59,75.11 73.63,75.11 72.78,75.96 71.56,75.96 70.87,75.26 59.72,75.26 v1(57.02,72.57)
  BOTTOM w0.114: v1(49.2,57.65) 49.3,57.65 50.31,58.67 v1(50.31,62.35)
P0_31: length 161.2
  TOP w0.114: R398.1 59.2,65.15 v1(58.44,65.9)
  TOP w0.152: v1(149.89,40.5) Q4.2
  L4_IN2 w0.114: v1(149.89,40.5) 149.89,15.69 147.86,13.66 140.24,13.66 138.9,12.32 82.17,12.32 62.76,31.72 62.76,32.11 62.25,32.62 62.25,38.73 64.47,40.95 64.47,43.22 64.1,43.6 64.1,60.25 v1(58.44,65.9)
P1_0: length 71.3
  TOP w0.114: U18.E17 98.61,68.16 v1(99.91,68.16)
  L3_IN1 w0.114: v1(99.91,68.16) 98.78,69.29 94.61,69.29 93.94,69.95 65.84,69.95 52.16,56.27 41.69,56.27 J27.5
P1_1: length 107.9
  TOP w0.114: v1(107.08,65.62) 106.65,66.06 100.5,66.06 100.11,65.66 96.83,65.66 U18.G15 ; C3.1 72.96,115.14 78.08,110.02 78.08,107.96 78.31,107.73 v1(87.8,107.73)
  TOP w0.152: R10.2 C3.1 56.74,116.65 SW1.2 SW1.1
  L4_IN2 w0.114: v1(87.8,107.73) 88.48,107.73 90.86,105.36 90.86,94.32 93.05,92.13 93.05,91.27 96.27,88.05 102.89,88.05 107.08,83.85 v1(107.08,65.62)
P1_2: length 68
  TOP w0.114: v1(89.16,72.43) 89.63,72.43 92.47,69.59 U18.A7
  L3_IN1 w0.114: J27.7 37.25,56.91 52.02,56.91 65.54,70.43 73.93,70.43 75.92,72.43 v1(89.16,72.43)
P1_3_SPI_CLK: length 125.5
  TOP w0.114: R74.1 16.39,47.62 30.43,47.62 44.02,34.03 68.98,34.03 70.1,35.15 80.21,35.15 82.08,37.02 v1(82.08,40.08) ; U18.G16 97.26,66.31 98.15,66.31 98.3,66.46 v1(98.91,66.46)
  BOTTOM w0.114: v1(98.91,66.46) 98.91,44.22 99.57,43.56 99.57,39.48 99.04,38.96 83.2,38.96 v1(82.08,40.08)
P1_4_SPI_MISO: length 126.2
  TOP w0.114: v1(99.8,66.28) 99.45,65.93 97.57,65.93 U18.G17 ; R75.1 18.47,48.08 30.62,48.08 44.43,34.27 65.67,34.27 v1(66.58,35.17) 66.58,35.16 67.33,34.41 68.98,34.41 69.96,35.39 80.11,35.39 81.74,37.02 81.74,39.3 v1(81.3,39.74)
  BOTTOM w0.114: R211.1 v1(66.58,35.17) ; v1(99.8,66.28) 99.53,66.01 99.53,57.06 100.04,56.55 100.04,54.32 99.31,53.59 99.31,44.32 100.08,43.56 100.08,39.24 99.31,38.48 82.56,38.48 v1(81.3,39.74)
P1_5_SPI_MOSI: length 183.5
  TOP w0.114: v1(81.3,37.84) 81.3,36.96 79.97,35.63 69.82,35.63 68.86,34.66 67.42,34.66 67.08,35 67.08,35.29 66.76,35.61 64.98,35.61 v1(64.67,35.3) 63.88,34.51 45.12,34.51 30.89,48.73 20.35,48.73 R76.1 ; U18.J16 97.23,64.77 104.4,64.77 105.16,65.52 106.04,65.52 v1(106.12,65.6)
  L3_IN1 w0.114: v1(95.2,87.66) 88.83,87.66 82.3,94.18 JP30.1
  L4_IN2 w0.114: v1(106.12,65.6) 106.28,65.76 106.28,82.8 101.43,87.66 v1(95.2,87.66)
  BOTTOM w0.114: R210.1 v1(64.67,35.3) ; v1(106.12,65.6) 106.12,44.02 99.94,37.84 v1(81.3,37.84)
P1_6_SPI_SS0: length 124.2
  TOP w0.114: v1(81.3,38.85) 80.86,38.42 80.86,36.87 79.87,35.87 68.29,35.87 67.53,35.11 v1(67.53,35.17) 67.53,35.18 66.86,35.85 62.17,35.85 61.07,34.75 45.77,34.75 31.24,49.28 R77.1 ; v1(103.44,65.32) 101.86,65.32 101.56,65.02 U18.J17
  BOTTOM w0.114: v1(103.44,65.32) 105.57,63.19 105.57,44.23 99.44,38.1 82.06,38.1 v1(81.3,38.85) ; R212.1 v1(67.53,35.17)
P1_7: length 239.1
  TOP w0.114: TP41.1 U32.3 148.05,14.93 v1(147.52,15.45) ; v1(100.93,65.57) 100.4,65.57 100.23,65.4 96.84,65.4 U18.J15
  L3_IN1 w0.114: v1(147.52,15.45) 146.78,16.2 145.96,16.2 145.45,15.69 87.94,15.69 v1(78.11,25.53) 68.48,35.16 v1(68.48,35.17) ; J28.2 26.26,52.23 42.04,52.23 42.99,53.18 42.99,54.86 44.12,56 52.22,56 65.94,69.71 93.55,69.71 94.22,69.03 98.19,69.03 100.93,66.3 v1(100.93,65.57)
  L4_IN2 w0.114: v1(100.93,65.57) 99.1,63.73 99.1,54.44 102.51,51.03 102.51,42.99 99.52,40.01 98.64,40.01 84.87,26.23 78.81,26.23 v1(78.11,25.53)
  BOTTOM w0.114: R213.1 v1(68.48,35.17)
